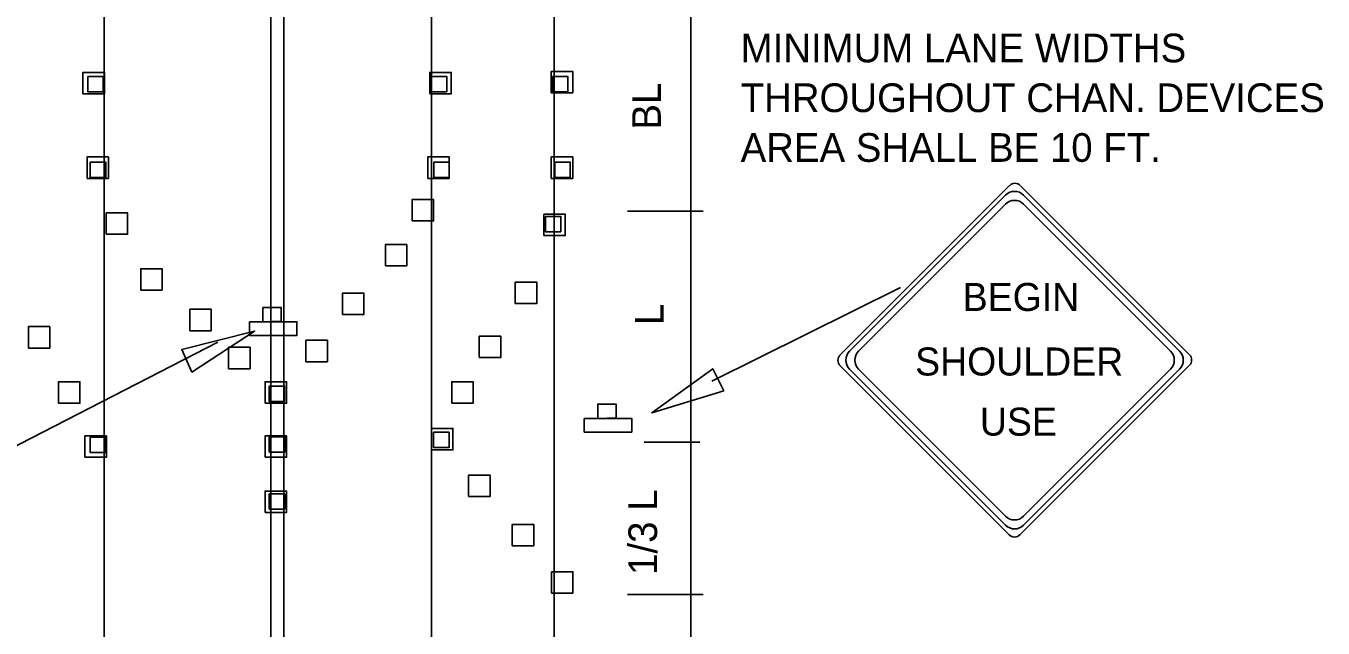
# Model space of a CAD drawing. Extents: x 1531.35 to 1538.58, y 1529.59 to 1539.23.
# Drawn here: x 1535.338 to 1538.05, y 1534.082 to 1535.34 of the extents above; entities that cross this region are included whole.
import ezdxf

# ---------------------------------------------------------------- set-up
doc = ezdxf.new("R2010")
doc.units = 0
for name, color, linetype in [('DETL-DIMS', 7, 'Continuous'), ('DETL-LINE', 7, 'Continuous'), ('DETL-NOTE', 7, 'Continuous'), ('USER-BORD', 7, 'Continuous')]:
    doc.layers.add(name, color=color, linetype=linetype)

# ---------------------------------------------------------------- blocks, each defined once
blk = doc.blocks.new('CD20')
at = {"layer": 'USER-BORD'}
blk.add_lwpolyline([(-0.0625, -0.0625), (0, -0.0625), (0, 0), (-0.0625, 0)], close=True, dxfattribs=at)
blk = doc.blocks.new('SIGN13')
at = {"layer": 'USER-BORD'}
for points in [[(-0.0134, 0.0182), (0.011, 0.0189), (0.011, 0.0371), (-0.0134, 0.0371)], [(-0.0314, 0.0182), (-0.0314, 0), (0.032, 0), (0.032, 0.0182)]]:
    blk.add_lwpolyline(points, close=True, dxfattribs=at)

msp = doc.modelspace()

# ---------------------------------------------------------------- linework, layer by layer
at = {"layer": 'DETL-DIMS'}
for p, q in [((1536.7279, 1535.3886), (1536.7279, 1533.0756)), ((1536.5957, 1534.9532), (1536.7538, 1534.9532)), ((1536.7721, 1534.5979), (1537.1664, 1534.7938)), ((1535.7395, 1534.6797), (1534.9003, 1534.2478)), ((1536.6306, 1534.4705), (1536.7471, 1534.4705)), ((1536.7279, 1534.3391), (1536.7279, 1532.0719)), ((1536.5957, 1534.1517), (1536.7538, 1534.1517))]:
    msp.add_line(p, q, dxfattribs=at)
for points in [[(1535.6846, 1534.6167), (1535.6639, 1534.664), (1535.8162, 1534.7024)], [(1536.7969, 1534.5775), (1536.7739, 1534.6238), (1536.6466, 1534.5316)]]:
    msp.add_lwpolyline(points, close=True, dxfattribs=at)
at = {"layer": 'DETL-LINE'}
for p, q in [((1535.5016, 1538.8924), (1535.5016, 1531.7496)), ((1535.8503, 1538.8924), (1535.8503, 1531.7496)), ((1535.8772, 1538.8924), (1535.8772, 1531.7496)), ((1536.4426, 1538.8924), (1536.4426, 1531.7496)), ((1536.1857, 1535.6352), (1536.1857, 1531.763)), ((1537.3948, 1535.007), (1537.0401, 1534.6523)), ((1537.0601, 1534.6606), (1537.3862, 1534.9868)), ((1537.7707, 1534.6531), (1537.4168, 1535.007)), ((1537.4239, 1534.9868), (1537.75, 1534.6606)), ((1537.3862, 1534.968), (1537.0789, 1534.6606)), ((1537.7312, 1534.6606), (1537.4239, 1534.968)), ((1537.7312, 1534.6606), (1537.7312, 1534.6606)), ((1537.0401, 1534.6303), (1537.3941, 1534.2764)), ((1537.3862, 1534.2968), (1537.0601, 1534.6229)), ((1537.0789, 1534.623), (1537.3862, 1534.3156)), ((1537.416, 1534.2764), (1537.7707, 1534.6311)), ((1537.75, 1534.6229), (1537.4239, 1534.2968)), ((1537.4239, 1534.3156), (1537.7312, 1534.6229))]:
    msp.add_line(p, q, dxfattribs=at)
for points in [[(1535.4572, 1535.1983), (1535.502, 1535.1983), (1535.502, 1535.2431), (1535.4572, 1535.2431)], [(1536.1824, 1535.1983), (1536.2272, 1535.1983), (1536.2272, 1535.2431), (1536.1824, 1535.2431)], [(1536.4364, 1535.2005), (1536.4812, 1535.2005), (1536.4812, 1535.2453), (1536.4364, 1535.2453)], [(1535.4658, 1535.0217), (1535.5106, 1535.0217), (1535.5106, 1535.0665), (1535.4658, 1535.0665)], [(1536.1782, 1535.0217), (1536.223, 1535.0217), (1536.223, 1535.0665), (1536.1782, 1535.0665)], [(1536.4364, 1535.0217), (1536.4812, 1535.0217), (1536.4812, 1535.0665), (1536.4364, 1535.0665)], [(1536.1454, 1534.9327), (1536.1902, 1534.9327), (1536.1902, 1534.9775), (1536.1454, 1534.9775)], [(1535.5058, 1534.9048), (1535.5506, 1534.9048), (1535.5506, 1534.9496), (1535.5058, 1534.9496)], [(1536.421, 1534.9021), (1536.4658, 1534.9021), (1536.4658, 1534.9469), (1536.421, 1534.9469)], [(1536.0896, 1534.8386), (1536.1344, 1534.8386), (1536.1344, 1534.8834), (1536.0896, 1534.8834)], [(1535.5779, 1534.7882), (1535.6227, 1534.7882), (1535.6227, 1534.833), (1535.5779, 1534.833)], [(1536.3611, 1534.7602), (1536.4059, 1534.7602), (1536.4059, 1534.805), (1536.3611, 1534.805)], [(1535.9999, 1534.7371), (1536.0447, 1534.7371), (1536.0447, 1534.7819), (1535.9999, 1534.7819)], [(1535.6808, 1534.7033), (1535.7256, 1534.7033), (1535.7256, 1534.7481), (1535.6808, 1534.7481)], [(1535.3431, 1534.6671), (1535.3879, 1534.6671), (1535.3879, 1534.7119), (1535.3431, 1534.7119)], [(1536.2858, 1534.6471), (1536.3306, 1534.6471), (1536.3306, 1534.6919), (1536.2858, 1534.6919)], [(1535.7617, 1534.6239), (1535.8065, 1534.6239), (1535.8065, 1534.6687), (1535.7617, 1534.6687)], [(1535.9234, 1534.6386), (1535.9682, 1534.6386), (1535.9682, 1534.6834), (1535.9234, 1534.6834)], [(1535.406, 1534.5518), (1535.4508, 1534.5518), (1535.4508, 1534.5966), (1535.406, 1534.5966)], [(1535.8381, 1534.5518), (1535.8829, 1534.5518), (1535.8829, 1534.5966), (1535.8381, 1534.5966)], [(1536.2282, 1534.5518), (1536.273, 1534.5518), (1536.273, 1534.5966), (1536.2282, 1534.5966)], [(1536.186, 1534.4543), (1536.2308, 1534.4543), (1536.2308, 1534.4991), (1536.186, 1534.4991)], [(1535.4614, 1534.4387), (1535.5062, 1534.4387), (1535.5062, 1534.4835), (1535.4614, 1534.4835)], [(1535.8381, 1534.4387), (1535.8829, 1534.4387), (1535.8829, 1534.4835), (1535.8381, 1534.4835)], [(1536.2636, 1534.3567), (1536.3084, 1534.3567), (1536.3084, 1534.4015), (1536.2636, 1534.4015)], [(1535.8381, 1534.3234), (1535.8829, 1534.3234), (1535.8829, 1534.3682), (1535.8381, 1534.3682)], [(1536.3549, 1534.2536), (1536.3997, 1534.2536), (1536.3997, 1534.2984), (1536.3549, 1534.2984)], [(1536.4369, 1534.1548), (1536.4817, 1534.1548), (1536.4817, 1534.1996), (1536.4369, 1534.1996)]]:
    msp.add_lwpolyline(points, close=True, dxfattribs=at)
for centre, radius, start, end in [((1537.4059, 1534.996), 0.0155, 45, 135), ((1537.4051, 1534.968), 0.0266, 45, 135), ((1537.4051, 1534.9492), 0.0266, 45, 135), ((1537.079, 1534.6418), 0.0266, 135, 225), ((1537.0977, 1534.6418), 0.0266, 135, 225), ((1537.7125, 1534.6418), 0.0266, 315, 45), ((1537.7313, 1534.6418), 0.0266, 315, 45), ((1537.0512, 1534.6413), 0.0155, 135, 225), ((1537.7599, 1534.6421), 0.0155, 315, 45), ((1537.4051, 1534.3344), 0.0266, 225, 315), ((1537.4051, 1534.3156), 0.0266, 225, 315), ((1537.4051, 1534.2874), 0.0155, 225, 315)]:
    msp.add_arc(centre, radius, start, end, dxfattribs=at)

# ---------------------------------------------------------------- block references
at = {"layer": 'DETL-LINE', "xscale": 0.5153677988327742, "yscale": -0.5153677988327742, "rotation": 180}
for p in [(1535.4676, 1535.2345), (1536.186, 1535.2345), (1536.439, 1535.2345), (1535.4725, 1535.0559), (1536.191, 1535.0559), (1536.444, 1535.0559), (1536.4244, 1534.9421), (1535.8466, 1534.5876), (1535.4723, 1534.4809)]:
    msp.add_blockref('CD20', p, dxfattribs=at)
at = {"layer": 'DETL-LINE'}
for name, p, xscale, yscale in [('SIGN13', (1535.8544, 1534.6934), 1.568744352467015, 1.5687443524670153), ('SIGN13', (1536.5545, 1534.4916), 1.568744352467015, 1.5687443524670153), ('CD20', (1535.8791, 1534.4816), 0.5153677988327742, 0.5153677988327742), ('CD20', (1536.2227, 1534.4911), 0.5153677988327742, 0.5153677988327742), ('CD20', (1535.8791, 1534.3622), 0.5153677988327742, 0.5153677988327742)]:
    msp.add_blockref(name, p, dxfattribs=dict(at, xscale=xscale, yscale=yscale))

# ---------------------------------------------------------------- texts
for s, p in [('BEGIN', (1537.2967, 1534.7446)), ('SHOULDER', (1537.1972, 1534.6097)), ('USE', (1537.3326, 1534.484))]:
    msp.add_text(s, height=0.05854, dxfattribs=at).set_placement(p)
at = {"layer": 'DETL-NOTE'}
for s, p in [('MINIMUM LANE WIDTHS', (1536.8324, 1535.2643)), ('THROUGHOUT CHAN. DEVICES', (1536.8324, 1535.1603)), ('AREA SHALL BE 10 FT.', (1536.8324, 1535.0563))]:
    msp.add_text(s, height=0.06, dxfattribs=at).set_placement(p)
for s, rotation, p in [('BL', 90.1133, (1536.6657, 1535.1237)), ('L', 90, (1536.6713, 1534.7149)), ('1/3 L', 90, (1536.6577, 1534.1929))]:
    msp.add_text(s, height=0.06, rotation=rotation, dxfattribs=at).set_placement(p)

doc.saveas('drawing.dxf')
